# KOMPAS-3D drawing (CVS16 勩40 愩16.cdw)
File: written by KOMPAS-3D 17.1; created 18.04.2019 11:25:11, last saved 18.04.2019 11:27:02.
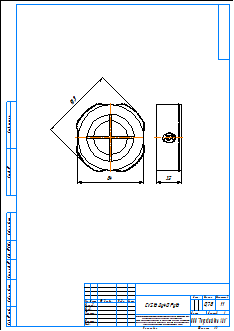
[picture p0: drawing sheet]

Sheet 1: A3, portrait

Title block, sheet 1: name: CVS16 Ду40 Ру16; material: Внимание! Данный продукт является объектом авторского права ООО «Торговый Дом АДЛ». / Запрещается изменение, копирование, распространение / (в том числе путем копирования на другие сайты и ресурсы в Интернете) / или любое иное использование информации и объектов без предварительного / согласия правообладателя (ООО «Торговый Дом АДЛ»).; mass: 0,78; sheets: 1; organisation: ООО "Торговый дом АДЛ"; sheet format: A3

Views: Спереди 1, Проекционный вид 3
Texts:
  user
Dimensions and other numbers on the sheet: 93,5; 84; 32; 1:1; 1; 0,78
